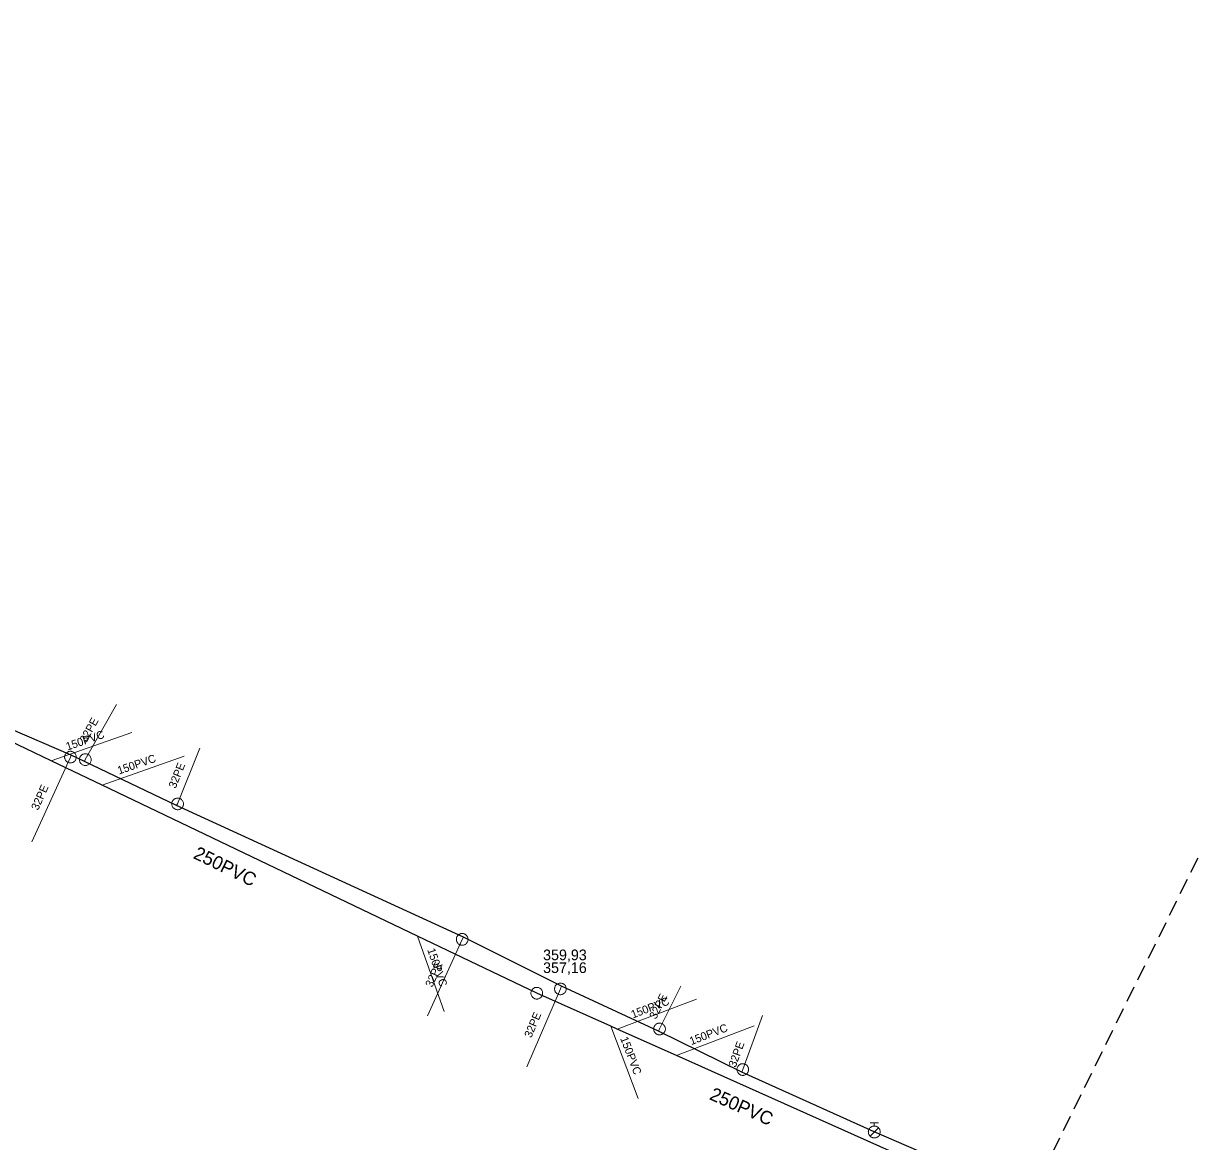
# Model space of a CAD drawing. Extents: x -741806 to -738704, y -1059275 to -1055387.
# Drawn here: x -740577.2 to -740489.7, y -1058217.7 to -1058133.8 of the extents above; entities that cross this region are included whole.
import ezdxf

# ---------------------------------------------------------------- set-up
doc = ezdxf.new("R2010")
doc.units = 0
doc.header["$LTSCALE"] = 0.4
doc.linetypes.add('MEDIUM_DASHED', pattern=[4.5, 3, -1.5])
for name, color, linetype, lineweight in [('2', 7, 'Continuous', 25), ('21', 7, 'Continuous', 13), ('3', 7, 'Continuous', 13), ('50', 7, 'Continuous', 13), ('51', 7, 'Continuous', 13), ('52', 7, 'Continuous', 25), ('56', 7, 'Continuous', 13), ('6', 7, 'Continuous', 13), ('63', 7, 'MEDIUM_DASHED', 25)]:
    doc.layers.add(name, color=color, linetype=linetype, lineweight=lineweight)
for name, color, linetype in [('5', 7, 'Continuous'), ('54', 7, 'Continuous'), ('55', 7, 'Continuous')]:
    doc.layers.add(name, color=color, linetype=linetype)

msp = doc.modelspace()

# ---------------------------------------------------------------- linework, layer by layer
at = {"layer": '2'}
for points in [[(-740538.76, -1058206.54), (-740547.691, -1058202.267), (-740571.346, -1058190.95), (-740575.151, -1058189.129), (-740580.188, -1058186.719), (-740583.26, -1058185.25)], [(-740505.91, -1058221.23), (-740528.296, -1058211.219), (-740532.724, -1058209.239), (-740533.221, -1058209.017), (-740538.76, -1058206.54)]]:
    msp.add_lwpolyline(points, dxfattribs=at)
at = {"layer": '21'}
for points in [[(-740572.673, -1058189.165), (-740572.6, -1058189.03), (-740570.27, -1058184.909)], [(-740565.754, -1058192.476), (-740565.68, -1058192.35), (-740564.01, -1058188.169)], [(-740573.656, -1058188.705), (-740573.717, -1058188.84), (-740576.6, -1058195.2)], [(-740544.259, -1058202.333), (-740544.35, -1058202.502), (-740546.94, -1058208.23)], [(-740536.912, -1058206.021), (-740536.991, -1058206.216), (-740539.5, -1058212.06)], [(-740529.642, -1058209.397), (-740529.559, -1058209.22), (-740527.96, -1058206)], [(-740523.39, -1058212.448), (-740523.32, -1058212.26), (-740521.829, -1058208.21)]]:
    msp.add_lwpolyline(points, dxfattribs=at)
at = {"layer": '3'}
msp.add_lwpolyline([(-740539.159, -1058206.36), (-740539.175, -1058206.403), (-740539.187, -1058206.446), (-740539.194, -1058206.492), (-740539.197, -1058206.537), (-740539.194, -1058206.583), (-740539.187, -1058206.629), (-740539.175, -1058206.673), (-740539.159, -1058206.716), (-740539.138, -1058206.756), (-740539.114, -1058206.795), (-740539.085, -1058206.831), (-740539.052, -1058206.864), (-740539.017, -1058206.892), (-740538.979, -1058206.917), (-740538.938, -1058206.938), (-740538.895, -1058206.955), (-740538.851, -1058206.966), (-740538.806, -1058206.974), (-740538.76, -1058206.976), (-740538.714, -1058206.974), (-740538.669, -1058206.966), (-740538.625, -1058206.955), (-740538.582, -1058206.938), (-740538.541, -1058206.918), (-740538.502, -1058206.893), (-740538.467, -1058206.864), (-740538.435, -1058206.832), (-740538.405, -1058206.796), (-740538.381, -1058206.758), (-740538.36, -1058206.717), (-740538.343, -1058206.675), (-740538.331, -1058206.631), (-740538.324, -1058206.585), (-740538.322, -1058206.539), (-740538.324, -1058206.494), (-740538.331, -1058206.448), (-740538.343, -1058206.404), (-740538.36, -1058206.361), (-740538.38, -1058206.321), (-740538.405, -1058206.282), (-740538.434, -1058206.247), (-740538.466, -1058206.213), (-740538.501, -1058206.185), (-740538.539, -1058206.16), (-740538.58, -1058206.139), (-740538.623, -1058206.122), (-740538.667, -1058206.11), (-740538.712, -1058206.103), (-740538.758, -1058206.101), (-740538.804, -1058206.104), (-740538.849, -1058206.111), (-740538.894, -1058206.122), (-740538.936, -1058206.139), (-740538.977, -1058206.159), (-740539.016, -1058206.184), (-740539.052, -1058206.213), (-740539.084, -1058206.245), (-740539.113, -1058206.281), (-740539.138, -1058206.319), (-740539.159, -1058206.359)], dxfattribs=at)
at = {"layer": '50'}
for p, q in [((-740513.768, -1058216.246), (-740513.46, -1058216.246)), ((-740513.46, -1058216.497), (-740513.46, -1058216.246)), ((-740513.153, -1058216.246), (-740513.46, -1058216.246)), ((-740513.46, -1058216.944), (-740513.777, -1058217.261)), ((-740513.46, -1058216.944), (-740513.144, -1058216.632))]:
    msp.add_line(p, q, dxfattribs=at)
msp.add_lwpolyline([(-740513.016, -1058216.948), (-740513.018, -1058216.899), (-740513.023, -1058216.853), (-740513.036, -1058216.807), (-740513.053, -1058216.764), (-740513.072, -1058216.724), (-740513.099, -1058216.683), (-740513.128, -1058216.648), (-740513.161, -1058216.613), (-740513.196, -1058216.583), (-740513.236, -1058216.559), (-740513.277, -1058216.537), (-740513.32, -1058216.518), (-740513.366, -1058216.508), (-740513.412, -1058216.5), (-740513.458, -1058216.497), (-740513.504, -1058216.5), (-740513.549, -1058216.505), (-740513.595, -1058216.518), (-740513.639, -1058216.535), (-740513.682, -1058216.556), (-740513.72, -1058216.581), (-740513.757, -1058216.61), (-740513.79, -1058216.643), (-740513.819, -1058216.678), (-740513.846, -1058216.718), (-740513.868, -1058216.759), (-740513.884, -1058216.802), (-740513.898, -1058216.848), (-740513.903, -1058216.894), (-740513.909, -1058216.94), (-740513.907, -1058216.988), (-740513.899, -1058217.034), (-740513.888, -1058217.077), (-740513.872, -1058217.123), (-740513.85, -1058217.164), (-740513.826, -1058217.204), (-740513.796, -1058217.239), (-740513.764, -1058217.274), (-740513.726, -1058217.304), (-740513.688, -1058217.328), (-740513.645, -1058217.35), (-740513.602, -1058217.366), (-740513.559, -1058217.38), (-740513.51, -1058217.388), (-740513.464, -1058217.391), (-740513.418, -1058217.388), (-740513.372, -1058217.38), (-740513.326, -1058217.369), (-740513.283, -1058217.353), (-740513.24, -1058217.331), (-740513.202, -1058217.307), (-740513.164, -1058217.277), (-740513.132, -1058217.245), (-740513.102, -1058217.21), (-740513.078, -1058217.169), (-740513.054, -1058217.129), (-740513.037, -1058217.085), (-740513.027, -1058217.04), (-740513.019, -1058216.994)], close=True, dxfattribs=at)
at = {"layer": '51'}
for points in [[(-740573.279, -1058188.84), (-740573.281, -1058188.795), (-740573.289, -1058188.75), (-740573.301, -1058188.705), (-740573.316, -1058188.663), (-740573.338, -1058188.622), (-740573.362, -1058188.583), (-740573.392, -1058188.548), (-740573.424, -1058188.515), (-740573.46, -1058188.487), (-740573.497, -1058188.462), (-740573.539, -1058188.441), (-740573.581, -1058188.424), (-740573.625, -1058188.412), (-740573.671, -1058188.405), (-740573.717, -1058188.403), (-740573.762, -1058188.405), (-740573.808, -1058188.412), (-740573.852, -1058188.424), (-740573.894, -1058188.441), (-740573.936, -1058188.462), (-740573.973, -1058188.487), (-740574.009, -1058188.515), (-740574.041, -1058188.548), (-740574.071, -1058188.583), (-740574.095, -1058188.622), (-740574.117, -1058188.663), (-740574.132, -1058188.705), (-740574.144, -1058188.75), (-740574.152, -1058188.795), (-740574.154, -1058188.841), (-740574.152, -1058188.886), (-740574.144, -1058188.931), (-740574.132, -1058188.976), (-740574.117, -1058189.018), (-740574.095, -1058189.059), (-740574.071, -1058189.098), (-740574.041, -1058189.133), (-740574.009, -1058189.166), (-740573.973, -1058189.194), (-740573.936, -1058189.219), (-740573.894, -1058189.24), (-740573.852, -1058189.257), (-740573.808, -1058189.268), (-740573.762, -1058189.276), (-740573.717, -1058189.278), (-740573.671, -1058189.276), (-740573.625, -1058189.268), (-740573.581, -1058189.257), (-740573.539, -1058189.24), (-740573.497, -1058189.219), (-740573.46, -1058189.194), (-740573.424, -1058189.166), (-740573.392, -1058189.133), (-740573.362, -1058189.098), (-740573.338, -1058189.059), (-740573.316, -1058189.018), (-740573.301, -1058188.976), (-740573.289, -1058188.931), (-740573.281, -1058188.886), (-740573.279, -1058188.841)], [(-740572.163, -1058189.03), (-740572.164, -1058188.985), (-740572.172, -1058188.94), (-740572.184, -1058188.895), (-740572.2, -1058188.853), (-740572.221, -1058188.812), (-740572.245, -1058188.773), (-740572.275, -1058188.738), (-740572.307, -1058188.705), (-740572.343, -1058188.677), (-740572.38, -1058188.652), (-740572.422, -1058188.631), (-740572.465, -1058188.614), (-740572.509, -1058188.602), (-740572.554, -1058188.595), (-740572.6, -1058188.593), (-740572.646, -1058188.595), (-740572.691, -1058188.602), (-740572.735, -1058188.614), (-740572.777, -1058188.631), (-740572.819, -1058188.652), (-740572.857, -1058188.677), (-740572.892, -1058188.705), (-740572.924, -1058188.738), (-740572.954, -1058188.773), (-740572.978, -1058188.812), (-740573, -1058188.853), (-740573.016, -1058188.895), (-740573.027, -1058188.94), (-740573.035, -1058188.985), (-740573.038, -1058189.031), (-740573.035, -1058189.076), (-740573.027, -1058189.121), (-740573.016, -1058189.166), (-740573, -1058189.208), (-740572.978, -1058189.249), (-740572.954, -1058189.288), (-740572.924, -1058189.323), (-740572.892, -1058189.356), (-740572.857, -1058189.384), (-740572.819, -1058189.409), (-740572.777, -1058189.43), (-740572.735, -1058189.447), (-740572.691, -1058189.458), (-740572.646, -1058189.466), (-740572.6, -1058189.468), (-740572.554, -1058189.466), (-740572.509, -1058189.458), (-740572.465, -1058189.447), (-740572.422, -1058189.43), (-740572.38, -1058189.409), (-740572.343, -1058189.384), (-740572.307, -1058189.356), (-740572.275, -1058189.323), (-740572.245, -1058189.288), (-740572.221, -1058189.249), (-740572.2, -1058189.208), (-740572.184, -1058189.166), (-740572.172, -1058189.121), (-740572.164, -1058189.076), (-740572.163, -1058189.031)], [(-740565.243, -1058192.35), (-740565.245, -1058192.305), (-740565.252, -1058192.26), (-740565.264, -1058192.215), (-740565.28, -1058192.173), (-740565.301, -1058192.132), (-740565.326, -1058192.093), (-740565.355, -1058192.058), (-740565.387, -1058192.025), (-740565.423, -1058191.997), (-740565.461, -1058191.972), (-740565.502, -1058191.951), (-740565.545, -1058191.934), (-740565.589, -1058191.922), (-740565.634, -1058191.915), (-740565.68, -1058191.913), (-740565.726, -1058191.915), (-740565.771, -1058191.922), (-740565.815, -1058191.934), (-740565.858, -1058191.951), (-740565.899, -1058191.972), (-740565.937, -1058191.997), (-740565.973, -1058192.025), (-740566.005, -1058192.058), (-740566.034, -1058192.093), (-740566.059, -1058192.132), (-740566.08, -1058192.173), (-740566.096, -1058192.215), (-740566.108, -1058192.26), (-740566.115, -1058192.305), (-740566.118, -1058192.351), (-740566.115, -1058192.396), (-740566.108, -1058192.441), (-740566.096, -1058192.486), (-740566.08, -1058192.528), (-740566.059, -1058192.569), (-740566.034, -1058192.608), (-740566.005, -1058192.643), (-740565.973, -1058192.676), (-740565.937, -1058192.704), (-740565.899, -1058192.729), (-740565.858, -1058192.75), (-740565.815, -1058192.767), (-740565.771, -1058192.778), (-740565.726, -1058192.786), (-740565.68, -1058192.788), (-740565.634, -1058192.786), (-740565.589, -1058192.778), (-740565.545, -1058192.767), (-740565.502, -1058192.75), (-740565.461, -1058192.729), (-740565.423, -1058192.704), (-740565.387, -1058192.676), (-740565.355, -1058192.643), (-740565.326, -1058192.608), (-740565.301, -1058192.569), (-740565.28, -1058192.528), (-740565.264, -1058192.486), (-740565.252, -1058192.441), (-740565.245, -1058192.396), (-740565.243, -1058192.351)], [(-740543.913, -1058202.502), (-740543.914, -1058202.457), (-740543.922, -1058202.412), (-740543.934, -1058202.367), (-740543.95, -1058202.325), (-740543.971, -1058202.284), (-740543.995, -1058202.245), (-740544.025, -1058202.21), (-740544.057, -1058202.177), (-740544.093, -1058202.149), (-740544.13, -1058202.124), (-740544.172, -1058202.103), (-740544.215, -1058202.086), (-740544.259, -1058202.074), (-740544.304, -1058202.067), (-740544.35, -1058202.065), (-740544.396, -1058202.067), (-740544.441, -1058202.074), (-740544.485, -1058202.086), (-740544.527, -1058202.103), (-740544.569, -1058202.124), (-740544.607, -1058202.149), (-740544.642, -1058202.177), (-740544.674, -1058202.21), (-740544.704, -1058202.245), (-740544.728, -1058202.284), (-740544.75, -1058202.325), (-740544.766, -1058202.367), (-740544.777, -1058202.412), (-740544.785, -1058202.457), (-740544.788, -1058202.503), (-740544.785, -1058202.548), (-740544.777, -1058202.593), (-740544.766, -1058202.638), (-740544.75, -1058202.68), (-740544.728, -1058202.721), (-740544.704, -1058202.76), (-740544.674, -1058202.795), (-740544.642, -1058202.828), (-740544.607, -1058202.856), (-740544.569, -1058202.881), (-740544.527, -1058202.902), (-740544.485, -1058202.919), (-740544.441, -1058202.93), (-740544.396, -1058202.938), (-740544.35, -1058202.94), (-740544.304, -1058202.938), (-740544.259, -1058202.93), (-740544.215, -1058202.919), (-740544.172, -1058202.902), (-740544.13, -1058202.881), (-740544.093, -1058202.856), (-740544.057, -1058202.828), (-740544.025, -1058202.795), (-740543.995, -1058202.76), (-740543.971, -1058202.721), (-740543.95, -1058202.68), (-740543.934, -1058202.638), (-740543.922, -1058202.593), (-740543.914, -1058202.548), (-740543.913, -1058202.503)], [(-740536.554, -1058206.216), (-740536.556, -1058206.171), (-740536.563, -1058206.126), (-740536.575, -1058206.081), (-740536.591, -1058206.039), (-740536.612, -1058205.998), (-740536.637, -1058205.959), (-740536.666, -1058205.924), (-740536.698, -1058205.891), (-740536.734, -1058205.863), (-740536.772, -1058205.838), (-740536.813, -1058205.817), (-740536.856, -1058205.8), (-740536.9, -1058205.788), (-740536.945, -1058205.781), (-740536.991, -1058205.779), (-740537.037, -1058205.781), (-740537.082, -1058205.788), (-740537.126, -1058205.8), (-740537.169, -1058205.817), (-740537.21, -1058205.838), (-740537.248, -1058205.863), (-740537.284, -1058205.891), (-740537.316, -1058205.924), (-740537.345, -1058205.959), (-740537.37, -1058205.998), (-740537.391, -1058206.039), (-740537.407, -1058206.081), (-740537.419, -1058206.126), (-740537.426, -1058206.171), (-740537.429, -1058206.217), (-740537.426, -1058206.262), (-740537.419, -1058206.307), (-740537.407, -1058206.352), (-740537.391, -1058206.394), (-740537.37, -1058206.435), (-740537.345, -1058206.474), (-740537.316, -1058206.509), (-740537.284, -1058206.542), (-740537.248, -1058206.57), (-740537.21, -1058206.595), (-740537.169, -1058206.616), (-740537.126, -1058206.633), (-740537.082, -1058206.644), (-740537.037, -1058206.652), (-740536.991, -1058206.654), (-740536.945, -1058206.652), (-740536.9, -1058206.644), (-740536.856, -1058206.633), (-740536.813, -1058206.616), (-740536.772, -1058206.595), (-740536.734, -1058206.57), (-740536.698, -1058206.542), (-740536.666, -1058206.509), (-740536.637, -1058206.474), (-740536.612, -1058206.435), (-740536.591, -1058206.394), (-740536.575, -1058206.352), (-740536.563, -1058206.307), (-740536.556, -1058206.262), (-740536.554, -1058206.217)], [(-740529.122, -1058209.22), (-740529.124, -1058209.175), (-740529.131, -1058209.13), (-740529.143, -1058209.085), (-740529.159, -1058209.043), (-740529.18, -1058209.002), (-740529.205, -1058208.963), (-740529.234, -1058208.928), (-740529.266, -1058208.895), (-740529.302, -1058208.867), (-740529.34, -1058208.842), (-740529.381, -1058208.821), (-740529.424, -1058208.804), (-740529.468, -1058208.792), (-740529.513, -1058208.785), (-740529.559, -1058208.783), (-740529.605, -1058208.785), (-740529.65, -1058208.792), (-740529.694, -1058208.804), (-740529.737, -1058208.821), (-740529.778, -1058208.842), (-740529.816, -1058208.867), (-740529.852, -1058208.895), (-740529.884, -1058208.928), (-740529.913, -1058208.963), (-740529.938, -1058209.002), (-740529.959, -1058209.043), (-740529.975, -1058209.085), (-740529.987, -1058209.13), (-740529.994, -1058209.175), (-740529.997, -1058209.221), (-740529.994, -1058209.266), (-740529.987, -1058209.311), (-740529.975, -1058209.356), (-740529.959, -1058209.398), (-740529.938, -1058209.439), (-740529.913, -1058209.478), (-740529.884, -1058209.513), (-740529.852, -1058209.546), (-740529.816, -1058209.574), (-740529.778, -1058209.599), (-740529.737, -1058209.62), (-740529.694, -1058209.637), (-740529.65, -1058209.648), (-740529.605, -1058209.656), (-740529.559, -1058209.658), (-740529.513, -1058209.656), (-740529.468, -1058209.648), (-740529.424, -1058209.637), (-740529.381, -1058209.62), (-740529.34, -1058209.599), (-740529.302, -1058209.574), (-740529.266, -1058209.546), (-740529.234, -1058209.513), (-740529.205, -1058209.478), (-740529.18, -1058209.439), (-740529.159, -1058209.398), (-740529.143, -1058209.356), (-740529.131, -1058209.311), (-740529.124, -1058209.266), (-740529.122, -1058209.221)], [(-740522.882, -1058212.26), (-740522.884, -1058212.215), (-740522.892, -1058212.17), (-740522.904, -1058212.125), (-740522.919, -1058212.083), (-740522.941, -1058212.042), (-740522.965, -1058212.003), (-740522.995, -1058211.968), (-740523.027, -1058211.935), (-740523.063, -1058211.907), (-740523.1, -1058211.882), (-740523.142, -1058211.861), (-740523.184, -1058211.844), (-740523.228, -1058211.832), (-740523.274, -1058211.825), (-740523.32, -1058211.823), (-740523.365, -1058211.825), (-740523.411, -1058211.832), (-740523.455, -1058211.844), (-740523.497, -1058211.861), (-740523.539, -1058211.882), (-740523.576, -1058211.907), (-740523.612, -1058211.935), (-740523.644, -1058211.968), (-740523.674, -1058212.003), (-740523.698, -1058212.042), (-740523.72, -1058212.083), (-740523.735, -1058212.125), (-740523.747, -1058212.17), (-740523.755, -1058212.215), (-740523.757, -1058212.261), (-740523.755, -1058212.306), (-740523.747, -1058212.351), (-740523.735, -1058212.396), (-740523.72, -1058212.438), (-740523.698, -1058212.479), (-740523.674, -1058212.518), (-740523.644, -1058212.553), (-740523.612, -1058212.586), (-740523.576, -1058212.614), (-740523.539, -1058212.639), (-740523.497, -1058212.66), (-740523.455, -1058212.677), (-740523.411, -1058212.688), (-740523.365, -1058212.696), (-740523.32, -1058212.698), (-740523.274, -1058212.696), (-740523.228, -1058212.688), (-740523.184, -1058212.677), (-740523.142, -1058212.66), (-740523.1, -1058212.639), (-740523.063, -1058212.614), (-740523.027, -1058212.586), (-740522.995, -1058212.553), (-740522.965, -1058212.518), (-740522.941, -1058212.479), (-740522.919, -1058212.438), (-740522.904, -1058212.396), (-740522.892, -1058212.351), (-740522.884, -1058212.306), (-740522.882, -1058212.261)]]:
    msp.add_lwpolyline(points, dxfattribs=at)
at = {"layer": '52'}
msp.add_lwpolyline([(-740375.044, -1058278.037), (-740378.824, -1058273.34), (-740394.89, -1058265.49), (-740400.5, -1058262.541), (-740409.548, -1058258.602), (-740416.798, -1058255.547), (-740435.443, -1058248.414), (-740442.241, -1058245.764), (-740464.396, -1058237.183), (-740473.081, -1058233.814), (-740479.142, -1058231.466), (-740486.337, -1058228.676), (-740513.46, -1058216.94), (-740523.39, -1058212.448), (-740529.642, -1058209.397), (-740536.912, -1058206.021), (-740544.259, -1058202.333), (-740565.754, -1058192.476), (-740572.673, -1058189.165), (-740573.656, -1058188.705), (-740595.099, -1058179.439), (-740602.27, -1058176.253), (-740623.44, -1058167.1), (-740623.879, -1058166.87)], dxfattribs=at)
at = {"layer": '56'}
for p, q in [((-740569.116, -1058187), (-740575.151, -1058189.129)), ((-740565.191, -1058188.777), (-740571.346, -1058190.95)), ((-740545.697, -1058207.916), (-740547.691, -1058202.267)), ((-740526.798, -1058206.975), (-740532.724, -1058209.239)), ((-740531.149, -1058214.439), (-740533.221, -1058209.017)), ((-740522.463, -1058208.99), (-740528.296, -1058211.219))]:
    msp.add_line(p, q, dxfattribs=at)
at = {"layer": '63'}
msp.add_lwpolyline([(-739961.423, -1056247.456), (-740265.345, -1057742.853), (-740265.345, -1057742.855), (-740574.897, -1058369.98)], dxfattribs=at)

# ---------------------------------------------------------------- texts
at = {"layer": '5'}
for rotation, p in [(334, (-740564.573, -1058196.391)), (336, (-740525.883, -1058214.472))]:
    msp.add_text('250PVC', height=1, rotation=rotation, dxfattribs=at).set_placement(p)
at = {"layer": '54'}
for rotation, p in [(61, (-740572.535, -1058187.814)), (68, (-740565.833, -1058191.231)), (66, (-740576.142, -1058192.878)), (66, (-740546.6, -1058206.144)), (64, (-740529.822, -1058208.53)), (67, (-740539.175, -1058209.93)), (70, (-740523.855, -1058212.143))]:
    msp.add_text('32PE', height=0.6, rotation=rotation, dxfattribs=at).set_placement(p)
at = {"layer": '55'}
for rotation, p in [(19, (-740573.94, -1058188.351)), (19, (-740570.075, -1058190.15)), (289, (-740546.98, -1058203.284)), (21, (-740531.56, -1058208.439)), (21, (-740527.178, -1058210.437)), (291, (-740532.518, -1058209.928))]:
    msp.add_text('150PVC', height=0.6, rotation=rotation, dxfattribs=at).set_placement(p)
at = {"layer": '6'}
for s, p in [('359,93', (-740538.287, -1058204.066)), ('357,16', (-740538.287, -1058205.026))]:
    msp.add_text(s, height=0.8, dxfattribs=at).set_placement(p)

doc.saveas('drawing.dxf')
